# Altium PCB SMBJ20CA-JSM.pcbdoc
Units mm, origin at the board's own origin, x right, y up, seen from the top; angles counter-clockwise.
Board outline 19.49 x 16.94 mm, 2 copper layers (Top Layer, Bottom Layer), stack 0 mm thick; 1 components, 0 nets, 2 pads, 0 vias.
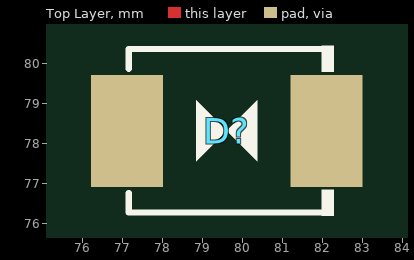
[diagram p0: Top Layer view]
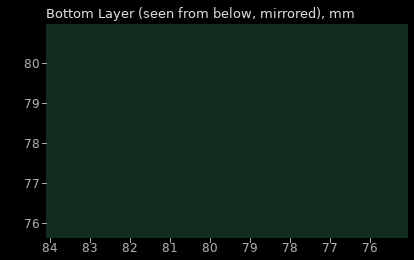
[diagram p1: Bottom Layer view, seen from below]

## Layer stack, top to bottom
Top Layer: signal copper (thickness not stored)
Bottom Layer: signal copper (thickness not stored)

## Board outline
89.34,69.85 69.85,69.85 69.85,86.795 89.34,86.795

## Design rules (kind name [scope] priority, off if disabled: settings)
PasteMaskExpansion "Paste Mask Expansion" [All] p1: expansion=0
SolderMaskExpansion "Solder Mask Expansion" [IsVia] p1: expansion=-25.4 istentingtop=TRUE
SolderMaskExpansion "Solder Mask Expansion" [All] p2: expansion=0.051 istentingtop=FALSE

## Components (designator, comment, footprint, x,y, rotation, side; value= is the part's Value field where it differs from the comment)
D? "SMBJ20CA-JSM" SMB_L4.8-W3.9-LS5.6-BI 79.595,78.322 r0 top

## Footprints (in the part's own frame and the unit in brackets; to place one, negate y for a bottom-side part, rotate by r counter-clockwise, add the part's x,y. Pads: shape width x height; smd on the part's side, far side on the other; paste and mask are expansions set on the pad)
SMB_L4.8-W3.9-LS5.6-BI [mm]
  rect 1.8x2.8 smd: 1(-2.495,0) 2(2.495,0)
  silkscreen extent -2.45,-2.12 2.68,2.12

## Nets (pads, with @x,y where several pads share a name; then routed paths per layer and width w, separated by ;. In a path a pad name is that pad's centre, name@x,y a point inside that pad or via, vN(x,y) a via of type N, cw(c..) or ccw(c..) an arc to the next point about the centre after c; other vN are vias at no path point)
pads on no net: D?.1 D?.2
